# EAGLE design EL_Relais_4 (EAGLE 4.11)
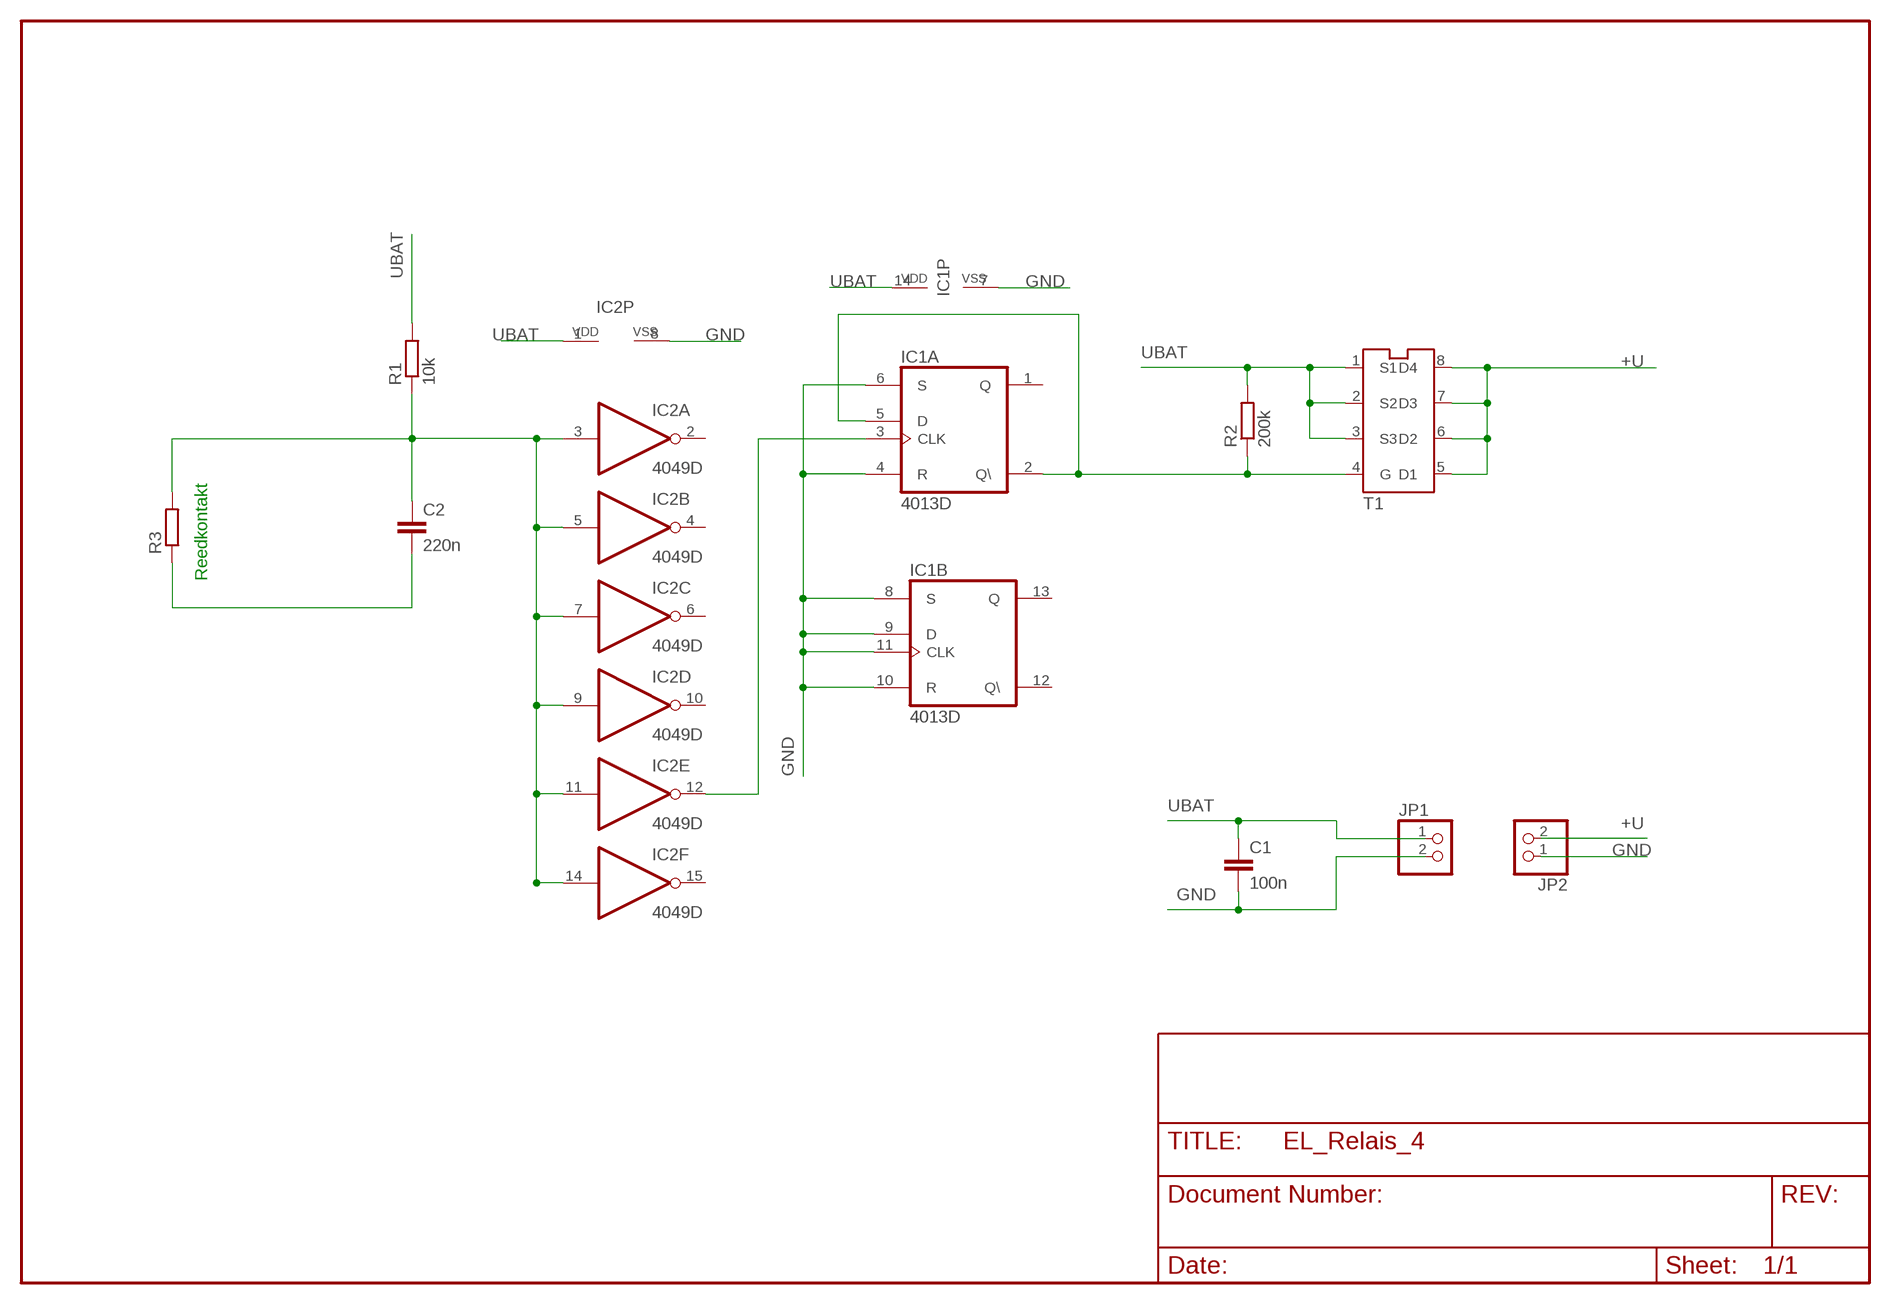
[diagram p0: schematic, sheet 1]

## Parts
C1  100n  C-EUC1206  [C1206]
C2  220n  C-EUC1210  [C1210]
IC1  4013D  [SO14]
IC2  4049D  [SO16]
JP1  PINHD-1X2  [1X02]
JP2  PINHD-1X2  [1X02]
R1  10k  R-EU_R1206  [R1206]
R2  200k  R-EU_R1206  [R1206]
R3  R-EU_0411/15  [0411/15]
T1  SI4425  [SO-8]

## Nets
+U: JP2.2 T1.5(D1) T1.6(D2) T1.7(D3) T1.8(D4)
GND: C1.2 C2.2 IC1.4(A:R) IC1.6(A:S) IC1.7(P:VSS) IC1.8(B:S) IC1.9(B:D) IC1.10(B:R) IC1.11(B:CLK) IC2.8(P:VSS) JP1.2 JP2.1 R3.1
N$1: IC1.3(A:CLK) IC2.12(E:O)
N$2: C2.1 IC2.3(A:I) IC2.5(B:I) IC2.7(C:I) IC2.9(D:I) IC2.11(E:I) IC2.14(F:I) R1.1 R3.2
N$4: IC1.2(A:Q\) IC1.5(A:D) R2.1 T1.4(G)
UBAT: C1.1 IC1.14(P:VDD) IC2.1(P:VDD) JP1.1 R1.2 R2.2 T1.1(S1) T1.2(S2) T1.3(S3)
Unconnected: IC1.1(A:Q) IC1.12(B:Q\) IC1.13(B:Q) IC2.2(A:O) IC2.4(B:O) IC2.6(C:O) IC2.10(D:O) IC2.15(F:O)

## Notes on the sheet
- Reedkontakt

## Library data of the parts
C1 C2 = rcl:C-EU: CAPACITOR, European symbol
IC1 = 40xx:4013: Dual D FLIP FLOP, set/reset
IC2 = 40xx:4049: Hex inverting BUFFER
JP1 JP2 = pinhead:PINHD-1X2: PIN HEADER
R1-R3 = rcl:R-EU_: RESISTOR, European symbol
T1 = transistor-fet:SI4425

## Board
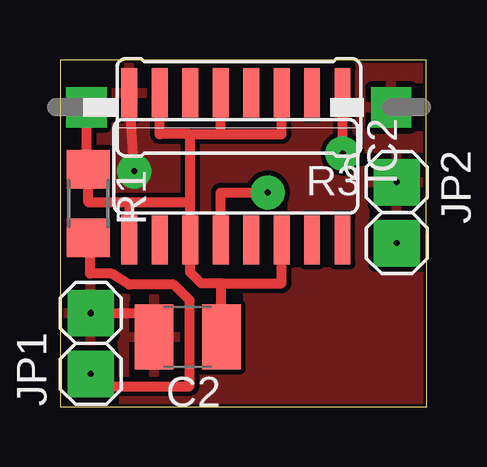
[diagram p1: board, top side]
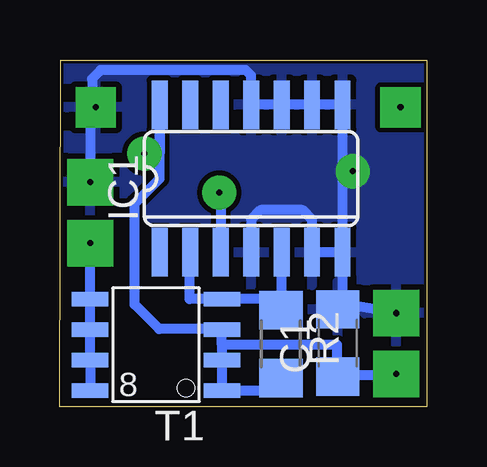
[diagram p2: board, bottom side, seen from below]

Size 15.29 x 14.47 mm. Coordinates in mm from the lower left corner, seen from the top.
Outline: 0,0 15.29,0 15.27,14.47 0,14.47 0,0
Copper layers (1*16): Top 0.035mm / dielectric 1.5mm / Bottom 0.035mm
Design rules "default": minimum track width 10mil, minimum drill 24mil, track to track 8mil, track to pad 8mil, pad to pad 8mil, via to via 8mil, smd to smd 8mil, copper to edge 5mil, drill to drill 8mil, minimum pad ring 10mil, minimum via ring 8mil, stop-mask expansion 4mil, vias tented up to drill 0mil, thermal gap 10mil

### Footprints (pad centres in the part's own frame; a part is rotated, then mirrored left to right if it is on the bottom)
C1206 = smd 1.6 x 1.8: 1 -1.4,0; 2 1.4,0
C1210 = smd 1.6 x 2.7: 1 -1.4,0; 2 1.4,0
SO14 = smd 0.66 x 2.032: 1 -3.81,-3.073; 2 -2.54,-3.073; 3 -1.27,-3.073; 4 0,-3.073; 5 1.27,-3.073; 6 2.54,-3.073; 7 3.81,-3.073; 8 3.81,3.073; 9 2.54,3.073; 10 1.27,3.073; 11 0,3.073; 12 -1.27,3.073; 13 -2.54,3.073; 14 -3.81,3.073
SO16 = smd 0.66 x 2.032: 1 -4.445,-3.073; 2 -3.175,-3.073; 3 -1.905,-3.073; 4 -0.635,-3.073; 5 0.635,-3.073; 6 1.905,-3.073; 7 3.175,-3.073; 8 4.445,-3.073; 9 4.445,3.073; 10 3.175,3.073; 11 1.905,3.073; 12 0.635,3.073; 13 -0.635,3.073; 14 -1.905,3.073; 15 -3.175,3.073; 16 -4.445,3.073
1X02 = drill 0.254 pad 1.93 square: 1 -1.27,0; 2 1.27,0
R1206 = smd 1.6 x 1.803: 1 -1.422,0; 2 1.422,0
0411/15 = drill 0.254 pad 1.676 square: 1 -6.35,0; 2 6.35,0
SO-8 = smd 1.524 x 0.61: 1 -2.743,1.27; 2 -2.743,0; 3 -2.743,-1.27; 4 -2.743,-2.54; 5 2.743,-2.54; 6 2.743,-1.27; 7 2.743,0; 8 2.743,1.27

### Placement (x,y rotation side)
C1  3.72,2.66 90 bottom
C2  5.32,2.92 180 top
IC1  7.33,9.52 0 bottom
IC2  7.33,10.03 180 top
JP1  1.28,2.64 90 top
JP2  14.03,8.1 270 top
R1  1.18,8.48 270 top
R2  6.08,2.61 270 bottom
R3  7.46,12.49 180 top
T1  11.29,1.95 180 bottom

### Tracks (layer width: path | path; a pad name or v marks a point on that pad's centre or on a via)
+U
  Bottom 0.406: T1.8 T1.7 T1.6 T1.5 JP2.2
GND  (via drill 0.25 pad 1.42)
  Top 0.406: v3.09,9.82 IC2.8 | JP1.2 3.95,3.91 3.95,2.99 C2.2
  Bottom 0.406: JP2.1 14.03,12.34 13.93,12.44 R3.1 13.98,12.47 13.96,12.49 13.96,13.69 13.6,14.04 7.56,14.04 7.33,13.81 IC1.11 IC1.10 IC1.9 IC1.8 | IC1.8 3.49,12.59 | IC1.7 IC1.6 4.79,7.79 5.17,8.2 6.95,8.2 7.33,7.82 IC1.4 | IC1.8 3.49,12.57 3.52,12.54 3.52,9.82 | IC1.7 3.52,9.82 | 3.52,9.82 v3.09,9.82 | 3.75,4.06 | 3.75,4.06 C1.2 | JP1.2 3.75,4.34 3.75,4.06 | C1.2 3.75,4.03 | IC1.7 3.52,4.26 C1.2
  pour Bottom: -0.06,14.42 -0.06,0.02 15.33,0.02 15.33,14.45 -0.04,14.45
  pour Top: 0.01,14.47 15.25,14.47 15.25,-0.03 0.01,-0.03
N$1  (via drill 0.25 pad 1.42)
  Top 0.406: IC2.12 6.69,8.94 v8.65,8.94
  Bottom 0.406: v8.65,8.94 8.6,8.91 IC1.3
N$2
  Top 0.406: R3.2 1.1,9.9 R1.1 1.18,8.53 2.88,8.53 | 3.72,8.53 2.88,8.53 | IC2.14 9.23,5.15 6.72,5.15 | 6.69,11.37 6.49,11.37 5.42,11.37 | IC2.7 4.15,11.37 5.42,11.37 | 5.42,8.53 IC2.11 5.42,5.61 5.88,5.15 6.72,5.15 | 5.42,8.53 4.18,8.53 | 4.18,8.53 4.15,8.53 | 5.42,8.53 5.42,11.37 | 6.72,5.15 6.72,5.13 C2.1 | IC2.3 9.23,11.37 6.69,11.37 | 2.88,8.53 IC2.9 | 3.72,8.53 | 4.18,8.53 3.72,8.53 | 6.69,11.37 | 6.69,11.37 | 6.69,11.37 IC2.5
N$4
  Bottom 0.406: T1.4 8.27,4.49 | T1.4 6.54,4.49 R2.1 6.06,4.06 IC1.5 | IC1.2 9.89,6.45 9.89,4.49 T1.4
UBAT  (via drill 0.25 pad 1.42)
  Top 0.406: R1.2 1.18,7.01 1.26,6.93 1.26,5.56 2.15,5.56 2.88,5.1 4.74,5.1 5.4,4.44 5.4,0.86 1.28,0.86 JP1.1 | v11.77,10.56 IC2.1
  Bottom 0.406: 6.08,1.24 R2.2 6.59,0.68 T1.1 | T1.1 8.27,0.68 | T1.2 8.24,1.98 | T1.2 T1.1 | 8.55,2.59 T1.2 | 8.55,2.59 T1.3 8.24,3.25 11.16,3.25 12.18,4.26 12.18,8.48 11.14,9.52 IC1.14 11.14,10.56 v11.77,10.56 | JP1.1 1.28,1.32 3.72,1.32 C1.1 3.75,1.26 3.75,2.59 8.55,2.59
